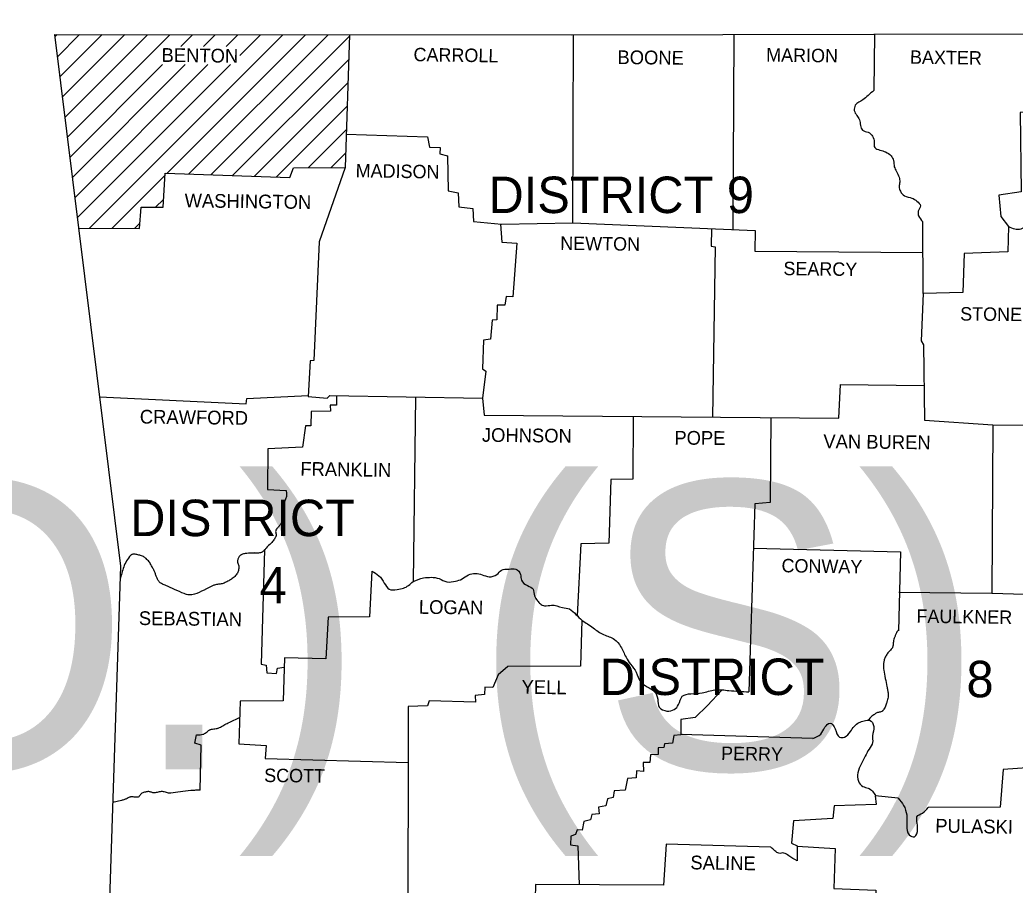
# Model space of a CAD drawing. Extents: x 6028647 to 6035072, y 5366486 to 5368495.
# Drawn here: x 6031060.6 to 6031371.9, y 5368087.3 to 5368357.9 of the extents above; entities that cross this region are included whole.
import ezdxf

# ---------------------------------------------------------------- set-up
doc = ezdxf.new("R2010")
doc.units = 0
doc.layers.add('Default', color=7, linetype='Continuous')

msp = doc.modelspace()

# ---------------------------------------------------------------- linework, layer by layer
at = {"layer": 'Default'}
for p, q in [((6031071.46, 5368352.54), (6031072.19, 5368353.27)), ((6031072.24, 5368346.25), (6031079.26, 5368353.27)), ((6031073.02, 5368339.96), (6031086.32, 5368353.26)), ((6031073.81, 5368333.67), (6031093.39, 5368353.26)), ((6031074.59, 5368327.38), (6031100.46, 5368353.25)), ((6031075.37, 5368321.1), (6031107.52, 5368353.25)), ((6031082.39, 5368292.75), (6031142.86, 5368353.23)), ((6031106.65, 5368309.95), (6031149.92, 5368353.22)), ((6031110.95, 5368349.6), (6031114.59, 5368353.24)), ((6031113.47, 5368309.7), (6031156.99, 5368353.22)), ((6031118.02, 5368349.6), (6031121.66, 5368353.24)), ((6031120.3, 5368309.46), (6031163.67, 5368352.83)), ((6031125.09, 5368349.6), (6031128.72, 5368353.23)), ((6031129.35, 5368346.79), (6031135.79, 5368353.23)), ((6031127.13, 5368309.21), (6031163.42, 5368345.5)), ((6031076.16, 5368314.81), (6031105.23, 5368343.88)), ((6031076.94, 5368308.52), (6031112.3, 5368343.88)), ((6031077.72, 5368302.23), (6031119.37, 5368343.88)), ((6031078.51, 5368295.94), (6031126.44, 5368343.88)), ((6031133.95, 5368308.97), (6031163.17, 5368338.18)), ((6031140.78, 5368308.72), (6031162.92, 5368330.86)), ((6031150.73, 5368311.6), (6031162.67, 5368323.54)), ((6031157.84, 5368311.64), (6031162.42, 5368316.22)), ((6031089.42, 5368292.72), (6031105.92, 5368309.22)), ((6031103.04, 5368299.27), (6031105.5, 5368301.73)), ((6031096.45, 5368292.68), (6031098.09, 5368294.32))]:
    msp.add_line(p, q, dxfattribs=at)
for points in [[(6031071.37, 5368353.27), (6031233.07, 5368353.17), (6031374.96, 5368353.47), (6031542.36, 5368356.07), (6031619.96, 5368357.87)], [(6031071.37, 5368353.27), (6031092.07, 5368187.07), (6031083.07, 5367915.77)], [(6031163.68, 5368353.21), (6031162.27, 5368311.67)], [(6031162.62, 5368322.1), (6031188.07, 5368321.27), (6031188.67, 5368318.07), (6031192.07, 5368317.97), (6031191.97, 5368315.97), (6031194.37, 5368315.37), (6031194.57, 5368304.47), (6031197.67, 5368303.77), (6031197.87, 5368299.47), (6031202.27, 5368298.87), (6031202.47, 5368294.87), (6031211.17, 5368293.97), (6031233.57, 5368294.47), (6031233.77, 5368353.17)], [(6031283.87, 5368353.28), (6031283.56, 5368292.37)], [(6031327.87, 5368353.37), (6031327.67, 5368335.77)], [(6031374.96, 5368353.47), (6031375.16, 5368329.07), (6031373.46, 5368328.97), (6031373.76, 5368304.07), (6031366.76, 5368303.07), (6031367.36, 5368296.37), (6031369.76, 5368293.27), (6031369.56, 5368285.37), (6031355.97, 5368284.87), (6031355.46, 5368272.67), (6031343.07, 5368272.27), (6031342.47, 5368257.47), (6031343.16, 5368256.27), (6031343.47, 5368232.67), (6031364.86, 5368231.27), (6031364.56, 5368178.57), (6031381.56, 5368178.07), (6031381.56, 5368124.47), (6031368.16, 5368123.47), (6031367.16, 5368111.67), (6031344.67, 5368111.57)], [(6031078.9, 5368292.77), (6031097.97, 5368292.67), (6031098.47, 5368299.27), (6031105.37, 5368299.27), (6031105.97, 5368309.97), (6031144.97, 5368308.57), (6031146.17, 5368311.57), (6031162.27, 5368311.67), (6031154.17, 5368288.47), (6031152.57, 5368251.37), (6031151.37, 5368251.27), (6031150.77, 5368240.07), (6031156.67, 5368239.57), (6031157.57, 5368240.47), (6031205.27, 5368239.57), (6031205.77, 5368234.27)], [(6031210.95, 5368293.99), (6031211.37, 5368288.37), (6031215.97, 5368288.07), (6031214.77, 5368271.27), (6031212.67, 5368271.37), (6031212.27, 5368268.67), (6031209.87, 5368268.67), (6031209.77, 5368264.07), (6031208.27, 5368263.97), (6031207.77, 5368258.07), (6031205.57, 5368257.77), (6031205.27, 5368248.77), (6031206.27, 5368248.07), (6031205.27, 5368239.57)], [(6031233.57, 5368294.47), (6031290.57, 5368292.07), (6031290.47, 5368285.57), (6031343.01, 5368285.17)], [(6031276.87, 5368292.65), (6031276.77, 5368287.17), (6031278.07, 5368286.87), (6031277.26, 5368233.69)], [(6031343.07, 5368272.27), (6031342.97, 5368294.77)], [(6031205.77, 5368234.27), (6031316.77, 5368233.37), (6031317.27, 5368243.87), (6031343.33, 5368243.57)], [(6031085.47, 5368239.99), (6031131.37, 5368237.87), (6031131.57, 5368239.47), (6031150.78, 5368240.38)], [(6031159.57, 5368240.43), (6031159.57, 5368237.37), (6031157.67, 5368237.37), (6031157.77, 5368235.57), (6031151.67, 5368235.47), (6031151.57, 5368230.97), (6031149.87, 5368230.97), (6031148.97, 5368224.27), (6031138.17, 5368223.77), (6031138.07, 5368211.07), (6031143.87, 5368210.67)], [(6031184.27, 5368239.97), (6031183.57, 5368182.27)], [(6031252.4, 5368233.89), (6031252.29, 5368214.3), (6031245.39, 5368214.2), (6031244.79, 5368194.3), (6031235.99, 5368194), (6031234.9, 5368171.57)], [(6031295.47, 5368233.54), (6031295.27, 5368206.97), (6031290.47, 5368206.57), (6031288.57, 5368147.77)], [(6031364.86, 5368231.27), (6031416.26, 5368230.97), (6031420.66, 5368233.07), (6031420.36, 5368193.97), (6031417.36, 5368192.67), (6031414.66, 5368190.37), (6031413.76, 5368189.47), (6031413.66, 5368178.27), (6031374.76, 5368178.27)], [(6031137.1, 5368192.15), (6031136.07, 5368156.47), (6031137.57, 5368156.07), (6031137.87, 5368153.67), (6031140.87, 5368153.47), (6031141.17, 5368155.17), (6031143.28, 5368155.52)], [(6031290.02, 5368192.68), (6031335.97, 5368191.57), (6031335.37, 5368166.87)], [(6031170.67, 5368185.47), (6031169.97, 5368171.17), (6031156.97, 5368171.07), (6031156.27, 5368158.07), (6031143.37, 5368158.37), (6031142.97, 5368144.97), (6031129.47, 5368144.87), (6031129.07, 5368131.47), (6031137.57, 5368130.97), (6031137.27, 5368126.87), (6031182.01, 5368125.63)], [(6031335.47, 5368178.97), (6031364.56, 5368178.57)], [(6031236.37, 5368170.17), (6031235.97, 5368155.77), (6031213.17, 5368155.67), (6031210.17, 5368153.07), (6031208.47, 5368149.07), (6031205.97, 5368149.27), (6031205.87, 5368146.97), (6031202.97, 5368146.67), (6031203.07, 5368144.57), (6031188.57, 5368144.97), (6031188.07, 5368143.37), (6031182.07, 5368143.17), (6031182.01, 5368125.63)], [(6031280.12, 5368148.3), (6031275.67, 5368143.47), (6031271.77, 5368139.77), (6031267.27, 5368139.07), (6031267.27, 5368134.37), (6031265.07, 5368134.07), (6031264.67, 5368131.67), (6031262.17, 5368131.47), (6031261.97, 5368130.37), (6031260.27, 5368130.27), (6031260.17, 5368128.17), (6031257.77, 5368128.07), (6031257.57, 5368125.67), (6031255.57, 5368125.67), (6031255.67, 5368122.87), (6031253.47, 5368123.07), (6031253.37, 5368120.87), (6031250.67, 5368120.67), (6031249.87, 5368117.07), (6031246.47, 5368116.77), (6031246.17, 5368114.77), (6031244.37, 5368114.27), (6031243.87, 5368112.17), (6031241.57, 5368111.67), (6031241.77, 5368109.57), (6031239.47, 5368109.37), (6031239.07, 5368107.77), (6031236.97, 5368107.17), (6031236.47, 5368104.47), (6031234.87, 5368104.57), (6031234.37, 5368103.17), (6031232.87, 5368102.67), (6031232.77, 5368099.97), (6031235.07, 5368099.57), (6031235.48, 5368087.4)], [(6031116.97, 5368116.97), (6031117.27, 5368131.07), (6031115.27, 5368131.67), (6031115.87, 5368134.37)], [(6031308.57, 5368133.17), (6031267.27, 5368134.47)], [(6031182.01, 5368125.63), (6031181.87, 5368084.67), (6031176.87, 5368084.57), (6031177.27, 5368081.57), (6031172.47, 5368081.67), (6031172.37, 5368079.47), (6031167.67, 5368079.47), (6031167.77, 5368077.87), (6031160.77, 5368077.67), (6031160.67, 5368071.57), (6031153.87, 5368072.17), (6031152.77, 5368022.97), (6031114.27, 5368023.07), (6031113.37, 5368011.67), (6031114.77, 5368010.67), (6031114.67, 5367997.87), (6031085.83, 5367999.14)], [(6031335.27, 5368114.47), (6031328.07, 5368115.27), (6031328.37, 5368112.57), (6031315.27, 5368112.07), (6031314.87, 5368108.17), (6031302.57, 5368107.47), (6031301.87, 5368100.47), (6031303.67, 5368099.57), (6031303.67, 5368094.97)], [(6031295.47, 5368099.17), (6031262.77, 5368100.17), (6031261.87, 5368087.27), (6031221.87, 5368087.47), (6031221.7, 5368083.15)], [(6031303.67, 5368099.52), (6031315.57, 5368098.77), (6031315.17, 5368086.27), (6031328.27, 5368085.77), (6031328.47, 5368074.87), (6031334.67, 5368074.37), (6031334.67, 5368072.47), (6031340.47, 5368072.07), (6031340.66, 5368065.07), (6031353.86, 5368065.07), (6031354.26, 5368058.17), (6031366.46, 5368057.57), (6031366.36, 5368044.55)]]:
    msp.add_lwpolyline(points, dxfattribs=at)
for points in [[(6031327.67, 5368335.77), (6031325.87, 5368334.27), (6031324.27, 5368332.87), (6031321.87, 5368331.17), (6031321.57, 5368329.57), (6031322.37, 5368327.97), (6031323.17, 5368326.67), (6031323.47, 5368324.87), (6031324.17, 5368323.37), (6031325.87, 5368322.77), (6031327.27, 5368321.47), (6031327.77, 5368319.67), (6031327.97, 5368317.97), (6031329.56, 5368317.17), (6031331.37, 5368316.57), (6031333.07, 5368315.37), (6031333.86, 5368313.87), (6031334.07, 5368311.97), (6031334.77, 5368310.47), (6031335.56, 5368308.67), (6031335.77, 5368307.17), (6031335.56, 5368305.67), (6031335.97, 5368304.27), (6031337.26, 5368302.87), (6031339.56, 5368302.17), (6031341.17, 5368301.17), (6031342.26, 5368299.77), (6031341.57, 5368298.07), (6031341.66, 5368296.57), (6031342.97, 5368294.77)], [(6031369.76, 5368293.27), (6031373.76, 5368292.57), (6031376.16, 5368293.47), (6031377.86, 5368290.87), (6031378.76, 5368288.87), (6031380.26, 5368285.97), (6031382.66, 5368285.07), (6031384.46, 5368283.47), (6031384.46, 5368281.77), (6031382.86, 5368280.17), (6031381.66, 5368278.57), (6031382.06, 5368276.67), (6031382.46, 5368274.07), (6031382.46, 5368271.57), (6031381.86, 5368269.27), (6031381.36, 5368267.17), (6031381.86, 5368265.37), (6031383.76, 5368265.67), (6031385.76, 5368267.17), (6031387.86, 5368267.17), (6031389.86, 5368266.07), (6031391.96, 5368264.17), (6031394.06, 5368264.57), (6031395.76, 5368265.07), (6031398.16, 5368265.77), (6031399.86, 5368264.87), (6031401.36, 5368263.67), (6031403.16, 5368261.77), (6031404.86, 5368260.57), (6031407.06, 5368259.47), (6031409.76, 5368258.77), (6031412.26, 5368257.07), (6031412.66, 5368254.17), (6031412.56, 5368251.67), (6031412.36, 5368248.57), (6031412.16, 5368245.17), (6031412.46, 5368241.87), (6031413.56, 5368239.67), (6031414.96, 5368237.07), (6031415.36, 5368234.67), (6031415.26, 5368230.87)], [(6031143.87, 5368210.67), (6031143.95, 5368210.15), (6031143.99, 5368209.62), (6031143.87, 5368208.57), (6031143.68, 5368208.02), (6031143.47, 5368207.47), (6031143.26, 5368206.93), (6031143.07, 5368206.37), (6031142.57, 5368204.47), (6031142.57, 5368203.85), (6031142.72, 5368203.22), (6031142.87, 5368202.59), (6031142.9, 5368202.28), (6031142.87, 5368201.97), (6031142.5, 5368200.94), (6031141.97, 5368199.97), (6031141.66, 5368199.55), (6031141.3, 5368199.17), (6031140.95, 5368198.79), (6031140.67, 5368198.37), (6031140.58, 5368197.9), (6031140.67, 5368197.37), (6031140.76, 5368196.85), (6031140.67, 5368196.37), (6031140.51, 5368196.09), (6031140.34, 5368195.81), (6031139.99, 5368195.27), (6031139.6, 5368194.75), (6031139.17, 5368194.27), (6031137.57, 5368192.67), (6031136.93, 5368191.95), (6031136.58, 5368191.62), (6031136.39, 5368191.48), (6031136.28, 5368191.42), (6031136.17, 5368191.37), (6031135.55, 5368191.2), (6031134.92, 5368191.16), (6031134.29, 5368191.17), (6031133.98, 5368191.18), (6031133.67, 5368191.17), (6031132.62, 5368191.12), (6031131.57, 5368191.07), (6031131.02, 5368191.02), (6031130.49, 5368190.9), (6031129.97, 5368190.7), (6031129.72, 5368190.55), (6031129.47, 5368190.37), (6031129.13, 5368190.04), (6031128.91, 5368189.67), (6031128.76, 5368189.28), (6031128.67, 5368188.87), (6031128.69, 5368188.3), (6031128.86, 5368187.72), (6031129.03, 5368187.14), (6031129.07, 5368186.57), (6031128.97, 5368186), (6031128.83, 5368185.44), (6031128.27, 5368184.37), (6031127.28, 5368183.4), (6031126.17, 5368182.67), (6031125.04, 5368182.06), (6031123.87, 5368181.57), (6031123.27, 5368181.45), (6031122.65, 5368181.4), (6031122.04, 5368181.33), (6031121.47, 5368181.17), (6031120.63, 5368180.79), (6031119.81, 5368180.38), (6031118.99, 5368179.97), (6031118.17, 5368179.57), (6031115.17, 5368178.27), (6031114.38, 5368178.09), (6031113.56, 5368178.07), (6031112.74, 5368178.21), (6031111.97, 5368178.47), (6031108.97, 5368179.77), (6031106.27, 5368180.97), (6031105.7, 5368181.21), (6031105.15, 5368181.45), (6031104.62, 5368181.76), (6031104.38, 5368181.95), (6031104.27, 5368182.05), (6031104.17, 5368182.17), (6031103.6, 5368183.04), (6031103.2, 5368183.98), (6031102.87, 5368184.94), (6031102.68, 5368185.41), (6031102.47, 5368185.87), (6031101.93, 5368186.88), (6031101.37, 5368187.87), (6031100.98, 5368188.44), (6031100.54, 5368188.95), (6031100.04, 5368189.43), (6031099.76, 5368189.65), (6031099.47, 5368189.87), (6031098.91, 5368190.19), (6031098.34, 5368190.4), (6031097.75, 5368190.55), (6031097.17, 5368190.67), (6031096.68, 5368190.77), (6031096.18, 5368190.82), (6031095.69, 5368190.75), (6031095.47, 5368190.64), (6031095.36, 5368190.56), (6031095.27, 5368190.47), (6031093.92, 5368188.68), (6031093.05, 5368186.83), (6031092.45, 5368184.92), (6031091.93, 5368182.97)], [(6031170.67, 5368185.47), (6031172.87, 5368184.07), (6031174.57, 5368181.77), (6031176.07, 5368179.87), (6031178.57, 5368179.77), (6031180.57, 5368180.17), (6031183.57, 5368182.27)], [(6031183.57, 5368182.27), (6031186.87, 5368183.37), (6031189.27, 5368183.57), (6031191.67, 5368183.17), (6031194.17, 5368182.17), (6031196.87, 5368182.37), (6031198.87, 5368183.07), (6031200.87, 5368184.37), (6031203.07, 5368184.77), (6031205.17, 5368184.37), (6031207.37, 5368183.77), (6031209.77, 5368184.47), (6031211.17, 5368185.77), (6031213.57, 5368186.17), (6031215.67, 5368186.17), (6031217.17, 5368184.47), (6031217.47, 5368182.67), (6031219.37, 5368180.97), (6031221.07, 5368179.87), (6031221.57, 5368177.77), (6031222.47, 5368176.27), (6031223.37, 5368175.27), (6031224.67, 5368174.67), (6031226.87, 5368174.87), (6031230.27, 5368174.17), (6031232.47, 5368173.67), (6031234.47, 5368171.97), (6031236.37, 5368170.17)], [(6031236.37, 5368170.17), (6031239.87, 5368167.77), (6031243.17, 5368165.67), (6031246.57, 5368164.17), (6031248.47, 5368161.97), (6031250.17, 5368158.57), (6031251.57, 5368156.47), (6031253.37, 5368153.87), (6031254.67, 5368150.97), (6031256.77, 5368149.37), (6031258.97, 5368147.97), (6031260.07, 5368145.47), (6031260.57, 5368142.97), (6031262.97, 5368141.77), (6031265.27, 5368142.27), (6031266.57, 5368143.77), (6031267.77, 5368146.37), (6031270.47, 5368147.17), (6031273.97, 5368147.47), (6031277.97, 5368148.37), (6031282.37, 5368148.17), (6031288.57, 5368147.77)], [(6031335.37, 5368166.87), (6031335.22, 5368166.91), (6031335.06, 5368166.78), (6031334.72, 5368166.17), (6031334.38, 5368165.34), (6031334.21, 5368164.93), (6031334.07, 5368164.57), (6031333.85, 5368163.81), (6031333.77, 5368163.04), (6031333.69, 5368162.28), (6031333.6, 5368161.92), (6031333.47, 5368161.57), (6031333.12, 5368161.07), (6031332.69, 5368160.61), (6031332.24, 5368160.17), (6031331.86, 5368159.67), (6031331.56, 5368159.14), (6031331.27, 5368158.61), (6031330.87, 5368157.47), (6031330.79, 5368157.11), (6031330.73, 5368156.75), (6031330.67, 5368156.02), (6031330.68, 5368155.29), (6031330.77, 5368154.57), (6031331.26, 5368151.97), (6031331.77, 5368149.47), (6031331.98, 5368148.32), (6031332.08, 5368147.75), (6031332.17, 5368147.17), (6031332.19, 5368146.45), (6031332.08, 5368145.72), (6031331.88, 5368145), (6031331.77, 5368144.63), (6031331.67, 5368144.27), (6031331.45, 5368143.59), (6031331.18, 5368142.94), (6031330.83, 5368142.33), (6031330.61, 5368142.05), (6031330.49, 5368141.91), (6031330.37, 5368141.77), (6031329.91, 5368141.49), (6031329.38, 5368141.37), (6031328.84, 5368141.28), (6031328.37, 5368141.07), (6031328.04, 5368140.84), (6031327.7, 5368140.6), (6031327.05, 5368140.11), (6031326.45, 5368139.57), (6031325.93, 5368138.95)], [(6031115.87, 5368134.37), (6031116.41, 5368134.3), (6031116.97, 5368134.31), (6031117.8, 5368134.48), (6031117.94, 5368134.52), (6031118.07, 5368134.57), (6031118.35, 5368134.71), (6031118.62, 5368134.88), (6031119.12, 5368135.28), (6031119.62, 5368135.68), (6031120.02, 5368135.91), (6031120.17, 5368135.97), (6031120.5, 5368136.07), (6031120.85, 5368136.14), (6031121.58, 5368136.24), (6031122.29, 5368136.35), (6031122.64, 5368136.44), (6031122.97, 5368136.57), (6031123.67, 5368136.94), (6031124.36, 5368137.33), (6031125.06, 5368137.72), (6031125.77, 5368138.07), (6031129.31, 5368139.69)], [(6031308.57, 5368133.17), (6031311.07, 5368134.57), (6031312.37, 5368136.67), (6031313.97, 5368137.97), (6031315.57, 5368136.17), (6031316.97, 5368133.57), (6031318.47, 5368133.57), (6031320.37, 5368135.37), (6031321.57, 5368136.97), (6031323.07, 5368138.17), (6031324.67, 5368138.67), (6031326.37, 5368138.87), (6031327.67, 5368136.97), (6031327.27, 5368133.97), (6031327.27, 5368131.97), (6031326.17, 5368129.87), (6031324.97, 5368127.67), (6031323.67, 5368125.17), (6031322.67, 5368122.47), (6031322.87, 5368119.87), (6031324.27, 5368118.17), (6031325.87, 5368117.67), (6031328.29, 5368115.25)], [(6031116.97, 5368116.97), (6031116.24, 5368116.98), (6031115.51, 5368116.97), (6031114.07, 5368116.87), (6031110.77, 5368116.47), (6031107.77, 5368116.07), (6031107.43, 5368116.06), (6031107.09, 5368116.1), (6031106.41, 5368116.27), (6031105.74, 5368116.47), (6031105.23, 5368116.56), (6031105.07, 5368116.57), (6031104.44, 5368116.52), (6031103.81, 5368116.38), (6031103.19, 5368116.24), (6031102.57, 5368116.17), (6031102.14, 5368116.23), (6031101.72, 5368116.37), (6031101.29, 5368116.5), (6031100.87, 5368116.57), (6031100.34, 5368116.54), (6031099.82, 5368116.44), (6031099.29, 5368116.28), (6031098.77, 5368116.07), (6031098.42, 5368115.81), (6031098.16, 5368115.45), (6031097.9, 5368115.1), (6031097.57, 5368114.87), (6031097.27, 5368114.8), (6031096.96, 5368114.79), (6031096.32, 5368114.87), (6031095.67, 5368114.94), (6031095.21, 5368114.91), (6031095.07, 5368114.87), (6031094.62, 5368114.69), (6031094.18, 5368114.46), (6031093.73, 5368114.25), (6031093.27, 5368114.07), (6031092.36, 5368113.81), (6031091.45, 5368113.57), (6031090.54, 5368113.39), (6031089.62, 5368113.25)], [(6031335.27, 5368114.47), (6031336.97, 5368112.27), (6031337.96, 5368109.27), (6031337.96, 5368105.87), (6031338.77, 5368103.07), (6031340.37, 5368102.47), (6031341.37, 5368104.87), (6031341.17, 5368107.27), (6031341.17, 5368108.67), (6031342.86, 5368109.87), (6031344.67, 5368111.57)], [(6031303.67, 5368094.97), (6031301.07, 5368096.47), (6031299.57, 5368097.37), (6031297.97, 5368097.27), (6031296.67, 5368098.07), (6031295.47, 5368099.17)]]:
    msp.add_spline(points, degree=3, dxfattribs=at)

# ---------------------------------------------------------------- texts
for s, height, rotation, p in [('BENTON', 4.301, 359.2527, (6031104.87, 5368344.77)), ('CARROLL', 4.201, 359.1481, (6031183.67, 5368344.97)), ('BOONE', 4.301, 359.4001, (6031247.47, 5368344.07)), ('MARION', 4.201, 359.1854, (6031293.97, 5368344.87)), ('BAXTER', 4.201, 359.2559, (6031338.96, 5368344.17)), ('MADISON', 4.201, 359.0906, (6031165.57, 5368308.67)), ('WASHINGTON', 4.3, 359.232, (6031112.07, 5368299.27)), ('NEWTON', 4.201, 359.2717, (6031229.57, 5368285.97)), ('SEARCY', 4.199, 359.2527, (6031299.37, 5368278.07)), ('STONE', 4.199, 359.4001, (6031354.66, 5368263.87)), ('CRAWFORD', 4.299, 359.2771, (6031098.07, 5368231.67)), ('JOHNSON', 4.301, 359.3514, (6031205.07, 5368225.97)), ('POPE', 4.301, 359.6155, (6031265.27, 5368225.07)), ('VAN BUREN', 4.301, 359.3508, (6031311.87, 5368223.97)), ('FRANKLIN', 4.301, 359.1815, (6031148.27, 5368215.37)), ('CONWAY', 4.199, 359.0371, (6031298.77, 5368185.17)), ('LOGAN', 4.301, 359.3969, (6031185.37, 5368172.17)), ('SEBASTIAN', 4.299, 359.2816, (6031097.77, 5368168.67)), ('FAULKNER', 4.201, 359.2486, (6031340.97, 5368169.37)), ('YELL', 4.301, 359.1987, (6031217.47, 5368147.17)), ('PERRY', 4.2, 359.0858, (6031279.87, 5368126.47)), ('SCOTT', 4.201, 359.4063, (6031136.97, 5368119.57)), ('PULASKI', 4.301, 359.0531, (6031346.86, 5368103.77)), ('SALINE', 4.301, 359.1491, (6031270.27, 5368092.27))]:
    msp.add_text(s, height=height, rotation=rotation, dxfattribs=at).set_placement(p)
for s, height, p in [('DISTRICT 9', 11.4, (6031207.17, 5368297.47)), ('(SEL. SECS.)  (BENTON CO.) (S)', 89.9998, (6029537.06, 5368123.49)), ('DISTRICT', 11.4, (6031095.08, 5368196.45)), ('4', 11.4, (6031135.58, 5368175.45)), ('DISTRICT', 11.4, (6031241.97, 5368146.77)), ('8', 11.4, (6031356.66, 5368146.07))]:
    msp.add_text(s, height=height, dxfattribs=at).set_placement(p)

doc.saveas('drawing.dxf')
